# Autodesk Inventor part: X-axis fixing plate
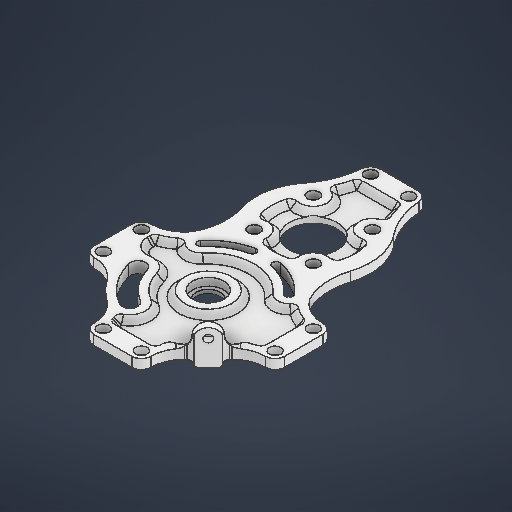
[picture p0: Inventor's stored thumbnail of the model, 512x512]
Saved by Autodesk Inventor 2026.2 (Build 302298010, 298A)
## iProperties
Created: 2026-04
Part Number: X-axis fixing plate
Material: PBT 플라스틱
Document SubType Name: Modeling
Designer: work
Density: 1.31 g/cm^3
Appearance: 매끄러움 - 흰색
Author: work
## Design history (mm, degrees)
sketch "스케치1"
  geometry: L1 (0, 0)-(0, -55); L2 (-15.5, -39.5)-(15.5, -39.5); L3 (15.5, -39.5)-(15.5, -70.5); L4 (15.5, -70.5)-(-15.5, -70.5); L5 (-15.5, -70.5)-(-15.5, -39.5); L6 (-15.5, -39.5)-(15.5, -70.5); L7 (15.5, -39.5)-(-15.5, -70.5); L8 (0, 0)-(22.981, -19.284); L9 (0, 0)-(30, 0); L10 (0, 0)-(6.237, -29.344); L11 (0, 0)-(-6.237, -29.344); L12 (-10, -95)-(10, -95); L13 (0, -55)-(0, -95); L14 (0, 0)-(45, 0); L15 (-10, -95)-(10, -95); L16 (-10, -100)-(10, -100); L17 (10, -90)-(-10, -90); L18 (10, 50)-(-10, 50); L19 (-10, 45)-(10, 45); L20 (-10, 45)-(10, 45); L21 (-10, 40)-(10, 40); L22 (0, 0)-(0, 45); L23 (0, 0)-(-45, 0); L24 (-45, -10)-(-45, 10); L25 (-40, -10)-(-40, 10); L26 (-50, 10)-(-50, -10); L27 (-45, -10)-(-45, 10); L28 (0, 0)-(0, -45); L29 (10, -45)-(-10, -45); L30 (10, -40)-(-10, -40); L31 (-10, -50)-(10, -50); L32 (10, -45)-(-10, -45); L33 (0, 0)-(45, 0); L34 (45, 10)-(45, -10); L35 (40, 10)-(40, -10); L36 (50, -10)-(50, 10); L37 (45, 10)-(45, -10); L38 (0, 0)-(-26.87, 26.87); L39 (-22.627, 31.113)-(-31.113, 22.627); L40 (-31.113, 22.627)-(-28.991, 20.506); L41 (-28.991, 20.506)-(-20.506, 28.991); L42 (-20.506, 28.991)-(-22.627, 31.113); L43 (0, 0)-(28.978, 7.765); L44 (0, 0)-(15, 25.981); C1 r 2.5 at (0, 0); C2 r 8.25 at (0, 0); C3 r 6.25 at (0, 0); C4 r 12.5 at (0, -55); C5 r 2 at (15.5, -39.5); C6 r 2 at (-15.5, -70.5); C7 r 2 at (15.5, -70.5); C8 r 2 at (-15.5, -39.5); C9 r 22 at (0, 0); C10 r 2 at (10, -95); C11 r 2 at (-10, -95); C12 r 2 at (10, 45); C13 r 2 at (-10, 45); C14 r 2 at (-45, 10); C15 r 2 at (-45, -10); C16 r 2 at (-10, -45); C17 r 2 at (10, -45); C18 r 2 at (45, -10); C19 r 2 at (45, 10); A1 r 30 centre (0, 0) between (6.237, -29.344) and (22.981, -19.284); A2 r 32 centre (0, 0) between (6.653, -31.301) and (24.513, -20.569); A3 r 28 centre (0, 0) between (5.822, -27.388) and (21.449, -17.998); A4 r 2 centre (6.237, -29.344) between (5.822, -27.388) and (6.653, -31.301); A5 r 2 centre (22.981, -19.284) between (24.513, -20.569) and (21.449, -17.998); A6 r 28 centre (0, 0) between (-21.449, -17.998) and (-5.822, -27.388); A7 r 30 centre (0, 0) between (-22.981, -19.284) and (-6.237, -29.344); A8 r 2 centre (-6.237, -29.344) between (-6.653, -31.301) and (-5.822, -27.388); A9 r 32 centre (0, 0) between (-24.513, -20.569) and (-6.653, -31.301); A10 r 2 centre (-22.981, -19.284) between (-21.449, -17.998) and (-24.513, -20.569); A11 r 38 centre (0, 0) between (22.258, 30.799) and (-26.87, 26.87); A12 r 30 centre (0, -55) between (-23.514, -73.63) and (28.562, -45.823); A13 r 5 centre (-10, -95) between (-10, -90) and (-10, -100); A14 r 5 centre (10, -95) between (10, -100) and (10, -90); A15 r 40 centre (-54.866, -98.471) between (-14.985, -95.386) and (-23.514, -73.63); A16 r 40 centre (54.866, -98.471) between (23.514, -73.63) and (14.985, -95.386); A17 r 5 centre (-10, 45) between (-10, 50) and (-10, 40); A18 r 5 centre (10, 45) between (10, 40) and (10, 50); A19 r 17.522 centre (32.522, 45) between (15, 45) and (22.258, 30.799); A20 r 17.522 centre (-32.522, 45) between (-22.258, 30.799) and (-15, 45); A21 r 17.522 centre (-45, -32.522) between (-30.799, -22.258) and (-45, -15); A22 r 5 centre (-45, -10) between (-50, -10) and (-40, -10); A23 r 5 centre (-45, 10) between (-40, 10) and (-50, 10); A24 r 17.522 centre (-45, 32.522) between (-45, 15) and (-30.799, 22.258); A25 r 17.522 centre (32.522, -45) between (22.258, -30.799) and (15, -45); A26 r 5 centre (10, -45) between (10, -50) and (10, -40); A27 r 5 centre (-10, -45) between (-10, -40) and (-10, -50); A28 r 17.522 centre (-32.522, -45) between (-15, -45) and (-22.258, -30.799); A29 r 17.522 centre (45, 32.522) between (30.799, 22.258) and (45, 15); A30 r 5 centre (45, 10) between (50, 10) and (40, 10); A31 r 5 centre (45, -10) between (40, -10) and (50, -10); A32 r 17.522 centre (45, -32.522) between (45, -15) and (30.799, -22.258); A33 r 30 centre (57.124, -36.646) between (30.799, -22.258) and (28.562, -45.823); A34 r 30 centre (-57.124, -36.646) between (-28.562, -45.823) and (-30.799, -22.258); A35 r 30 centre (0, 0) between (28.978, 7.765) and (15, 25.981); A36 r 34 centre (0, 0) between (32.841, 8.8) and (17, 29.445); A37 r 26 centre (0, 0) between (25.114, 6.729) and (13, 22.517); A38 r 4 centre (28.978, 7.765) between (25.114, 6.729) and (32.841, 8.8); A39 r 4 centre (15, 25.981) between (17, 29.445) and (13, 22.517); 17 further points
  constraints: 98 end point, 80 point on circle, 58 centre point, 23 coincident, 21 tangent, 14 symmetric about line, 8 midpoint, 7 equal length, 5 horizontal, 5 perpendicular, 3 vertical, 2 point on line, 121 other
  dimensions: "d0" = 5 diameter of C1; "d1" = 16.5 diameter of C2; "d2" = 2 radial gap between concentric circles of C2 C3; "d3" = 55 distance of L1.start L1.end; "d4" = 25 diameter of C4; "d5" = 31 distance of L3.end L4.end; "d6" = 31 distance of L2.end L3.end; "d7" = 4 diameter of C5; "d9" = 4 diameter of C6; "d10" = 4 diameter of C7; "d11" = 4 diameter of C8; "d14" = 44 diameter of C9; "d15" = 30 radius of A1; "d16" = 40 deg angle of L8 L9; "d17" = 38 deg angle of L10 L8; "d18" = 4 diameter of A4; "d19" = 8 radial gap between concentric circles of A11 A1; "d20" = 60 diameter of A12; "d21" = 20 distance of L12.start L12.end; "d22" = 45 distance of L14.start L14.end; "d23" = 40 distance of L13.start L13.end; "d24" = 4 diameter of C10; "d25" = 4 diameter of C11; "d26" = 5 radius of A14; "d27" = 40 radius of A15; "d28" = 20 distance of L20.start L20.end; "d29" = 4 diameter of C12; "d30" = 4 diameter of C13; "d31" = 5 radius of A18; "d32" = 45 distance of L14.start L22.end; "d35" = 360 deg dimension on C9.centre L22.end (derived); "d37" = 30 radius of A33; "d38" = 45 deg angle of L22 L38; "d39" = 12 distance of L40.end L41.end; "d40" = 3 distance of L39.end L40.end; "d41" = 30 radius of A35; "d42" = 45 deg angle of L43 L44; "d43" = 8 diameter of A38; "d44" = 30 deg angle of L22 L44
  node "스케치 - 원형 패턴1" dims "d35" = 360 deg (derived)
extrude "돌출1" new body sketch "스케치1" distance "d45" = 6; taper "d46" = 0 deg
extrude "돌출2" join sketch "스케치1" distance "d47" = 18; taper "d48" = 0 deg
extrude "돌출3" join sketch "스케치1" distance "d49" = 2; taper "d50" = 0 deg
sketch "스케치2"
  geometry: L1 (-50, 10)-(-50, -10) reference; L2 (-10, -50)-(10, -50) reference; L3 (22.29, -30.776)-(20.506, -28.991) reference; L4 (20.506, -28.991)-(28.991, -20.506) reference; L5 (28.991, -20.506)-(30.776, -22.29) reference; L6 (50, -10)-(50, 10) reference; L7 (10, 100)-(-10, 100) reference; C1 r 2 at (10, 95) reference; C2 r 2 at (-10, 95) reference; C3 r 2 at (10, -45) reference; C4 r 2 at (-10, -45) reference; C5 r 2 at (45, 10) reference; C6 r 2 at (45, -10) reference; C7 r 2 at (-45, -10) reference; C8 r 2 at (-45, 10) reference; C9 r 12.5 at (0, 55) reference; C10 r 2 at (-15.5, 39.5) reference; C11 r 2 at (15.5, 70.5) reference; C12 r 2 at (-15.5, 70.5) reference; C13 r 2 at (15.5, 39.5) reference; C14 r 8.25 at (0, 0) reference; A1 r 17.522 centre (-45, 32.522) between (-45, 15) and (-30.799, 22.258) reference; A2 r 5 centre (-45, 10) between (-45, 15) and (-50, 10) reference; A3 r 5 centre (-45, -10) between (-50, -10) and (-45, -15) reference; A4 r 17.522 centre (-45, -32.522) between (-30.799, -22.258) and (-45, -15) reference; A5 r 38 centre (0, 0) between (-30.799, -22.258) and (-22.258, -30.799) reference; A6 r 17.522 centre (-32.522, -45) between (-15, -45) and (-22.258, -30.799) reference; A7 r 5 centre (-10, -45) between (-15, -45) and (-10, -50) reference; A8 r 5 centre (10, -45) between (10, -50) and (15, -45) reference; A9 r 17.522 centre (32.522, -45) between (22.258, -30.799) and (15, -45) reference; A10 r 38 centre (0, 0) between (22.258, -30.799) and (22.29, -30.776) reference; A11 r 38 centre (0, 0) between (30.776, -22.29) and (30.799, -22.258) reference; A12 r 17.522 centre (45, -32.522) between (45, -15) and (30.799, -22.258) reference; A13 r 5 centre (45, -10) between (45, -15) and (50, -10) reference; A14 r 5 centre (45, 10) between (50, 10) and (45, 15) reference; A15 r 17.522 centre (45, 32.522) between (30.799, 22.258) and (45, 15) reference; A16 r 30 centre (57.124, 36.646) between (28.562, 45.823) and (30.799, 22.258) reference; A17 r 30 centre (0, 55) between (28.562, 45.823) and (23.514, 73.63) reference; A18 r 40 centre (54.866, 98.471) between (14.985, 95.386) and (23.514, 73.63) reference; A19 r 5 centre (10, 95) between (14.985, 95.386) and (10, 100) reference; A20 r 5 centre (-10, 95) between (-10, 100) and (-14.985, 95.386) reference; A21 r 40 centre (-54.866, 98.471) between (-23.514, 73.63) and (-14.985, 95.386) reference; A22 r 30 centre (0, 55) between (-23.514, 73.63) and (-28.562, 45.823) reference; A23 r 32 centre (0, 0) between (24.513, 20.569) and (6.653, 31.301) reference; A24 r 2 centre (22.981, 19.284) between (21.449, 17.998) and (24.513, 20.569) reference; A25 r 28 centre (0, 0) between (21.449, 17.998) and (5.822, 27.388) reference; A26 r 2 centre (6.237, 29.344) between (6.653, 31.301) and (5.822, 27.388) reference; A27 r 32 centre (0, 0) between (-6.653, 31.301) and (-24.513, 20.569) reference; A28 r 2 centre (-6.237, 29.344) between (-5.822, 27.388) and (-6.653, 31.301) reference; A29 r 28 centre (0, 0) between (-5.822, 27.388) and (-21.449, 17.998) reference; A30 r 2 centre (-22.981, 19.284) between (-24.513, 20.569) and (-21.449, 17.998) reference; A31 r 26 centre (0, 0) between (-25.114, -6.729) and (-13, -22.517) reference; A32 r 4 centre (-15, -25.981) between (-17, -29.445) and (-13, -22.517) reference; A33 r 34 centre (0, 0) between (-32.841, -8.8) and (-17, -29.445) reference; A34 r 4 centre (-28.978, -7.765) between (-25.114, -6.729) and (-32.841, -8.8) reference; A35 r 30 centre (-57.124, 36.646) between (-30.799, 22.258) and (-28.562, 45.823) reference; 11 further points
  constraints: 10 coincident
hole "구멍1" sketch "스케치2" at (-10, -45), (10, -45), (-45, -10), (-45, 10), (15.5, 39.5), (-15.5, 39.5), (15.5, 70.5), (-15.5, 70.5), (10, 95), (-10, 95), (45, 10), (45, -10) diameter "d51" = 4; stored, may be unused: countersink angle "d55" = 90 deg, drill point angle "d57" = 0 deg; dims "d52" = 6, "d53" = 6.2, "d54" = 4, "d56" = 8
sketch "스케치3"
  geometry: L1 (-6, 0)-(-6, 18); L2 (-12, 18)-(0, 18) reference; C1 r 2 at (-6, 13)
  constraints: 2 end point, 1 centre point, 1 midpoint, 1 point on line
  dimensions: "d58" = 4 diameter of C1; "d59" = 5 distance from line of L2 C1.centre
extrude "돌출4" cut sketch "스케치3" distance "d60" = 6; taper "d61" = 0 deg
fillet "모깎기1" dims "d62" = 6
sketch "스케치4"
  geometry: L1 (16.263, -33.234)-(18.091, -35.062) reference; L2 (16.263, -33.234)-(33.234, -16.263) reference; L3 (35.062, -18.091)-(33.234, -16.263) reference; L4 (50, -10)-(50, 10) reference; L5 (10, 100)-(-10, 100) reference; L6 (-50, 10)-(-50, -10) reference; L7 (-10, -50)-(10, -50) reference; L8 (-10, 96)-(10, 96); L9 (46, 10)-(46, -10); L10 (35.727, -13.1)-(33.234, -10.607); L11 (33.234, -10.607)-(10.607, -33.234); L12 (10.607, -33.234)-(13.1, -35.727); L13 (10, -46)-(-10, -46); L14 (-46, -10)-(-46, 10); L15 (-10, -45)-(10, -45); L16 (-10, -40)-(10, -40); L17 (10, -50)-(-10, -50); L18 (-45, -10)-(-45, 10); L19 (-40, -10)-(-40, 10); L20 (-50, 10)-(-50, -10); L21 (45, -10)-(45, 10); L22 (50, -10)-(50, 10); L23 (40, 10)-(40, -10); L24 (10, 95)-(-10, 95); L25 (10, 100)-(-10, 100); L26 (-10, 90)-(10, 90); L27 (0, 55)-(0, 0); C1 r 6.25 at (0, 0) reference; C2 r 12.25 at (0, 0); C3 r 8.25 at (0, 0) reference; C4 r 8.25 at (0, 0) reference; C5 r 12.5 at (0, 55) reference; C6 r 3.1 at (-10, -45) reference; C7 r 3.1 at (10, -45) reference; C8 r 3.1 at (-45, -10) reference; C9 r 3.1 at (-45, 10) reference; C10 r 3.1 at (15.5, 39.5) reference; C11 r 3.1 at (-15.5, 39.5) reference; C12 r 3.1 at (15.5, 70.5) reference; C13 r 3.1 at (-15.5, 70.5) reference; C14 r 3.1 at (10, 95) reference; C15 r 3.1 at (-10, 95) reference; C16 r 3.1 at (45, 10) reference; C17 r 3.1 at (45, -10) reference; C18 r 36 at (0, 0); C19 r 7.1 at (-15.5, 39.5); C20 r 7.1 at (-15.5, 70.5); C21 r 7.1 at (15.5, 70.5); C22 r 2 at (-10, -45) reference; C23 r 2 at (-45, -10) reference; A1 r 26 centre (0, 0) between (-25.114, -6.729) and (-13, -22.517) reference; A2 r 4 centre (-15, -25.981) between (-17, -29.445) and (-13, -22.517) reference; A3 r 34 centre (0, 0) between (-32.841, -8.8) and (-17, -29.445) reference; A4 r 4 centre (-28.978, -7.765) between (-25.114, -6.729) and (-32.841, -8.8) reference; A5 r 32 centre (0, 0) between (-6.653, 31.301) and (-24.513, 20.569) reference; A6 r 2 centre (-6.237, 29.344) between (-5.822, 27.388) and (-6.653, 31.301) reference; A7 r 28 centre (0, 0) between (-5.822, 27.388) and (-21.449, 17.998) reference; A8 r 2 centre (-22.981, 19.284) between (-24.513, 20.569) and (-21.449, 17.998) reference; A9 r 32 centre (0, 0) between (24.513, 20.569) and (6.653, 31.301) reference; A10 r 2 centre (22.981, 19.284) between (21.449, 17.998) and (24.513, 20.569) reference; A11 r 28 centre (0, 0) between (21.449, 17.998) and (5.822, 27.388) reference; A12 r 2 centre (6.237, 29.344) between (6.653, 31.301) and (5.822, 27.388) reference; A13 r 17.522 centre (45, -32.522) between (45, -15) and (35.062, -18.091) reference; A14 r 5 centre (45, -10) between (45, -15) and (50, -10) reference; A15 r 5 centre (45, 10) between (50, 10) and (45, 15) reference; A16 r 17.522 centre (45, 32.522) between (30.799, 22.258) and (45, 15) reference; A17 r 30 centre (57.124, 36.646) between (28.562, 45.823) and (30.799, 22.258) reference; A18 r 30 centre (0, 55) between (28.562, 45.823) and (23.514, 73.63) reference; A19 r 40 centre (54.866, 98.471) between (14.985, 95.386) and (23.514, 73.63) reference; A20 r 5 centre (10, 95) between (14.985, 95.386) and (10, 100) reference; A21 r 5 centre (-10, 95) between (-10, 100) and (-14.985, 95.386) reference; A22 r 40 centre (-54.866, 98.471) between (-23.514, 73.63) and (-14.985, 95.386) reference; A23 r 30 centre (0, 55) between (-23.514, 73.63) and (-28.562, 45.823) reference; A24 r 30 centre (-57.124, 36.646) between (-30.799, 22.258) and (-28.562, 45.823) reference; A25 r 17.522 centre (-45, 32.522) between (-45, 15) and (-30.799, 22.258) reference; A26 r 5 centre (-45, 10) between (-45, 15) and (-50, 10) reference; A27 r 5 centre (-45, -10) between (-50, -10) and (-45, -15) reference; A28 r 17.522 centre (-45, -32.522) between (-30.799, -22.258) and (-45, -15) reference; A29 r 38 centre (0, 0) between (-30.799, -22.258) and (-22.258, -30.799) reference; A30 r 17.522 centre (-32.522, -45) between (-15, -45) and (-22.258, -30.799) reference; A31 r 5 centre (-10, -45) between (-15, -45) and (-10, -50) reference; A32 r 5 centre (10, -45) between (10, -50) and (15, -45) reference; A33 r 17.522 centre (32.522, -45) between (18.091, -35.062) and (15, -45) reference; A34 r 22 centre (0, 0) between (-21.25, -5.694) and (-11, -19.053); A35 r 8 centre (-28.978, -7.765) between (-21.25, -5.694) and (-36.705, -9.835); A36 r 38 centre (0, 0) between (-36.705, -9.835) and (-19, -32.909); A37 r 8 centre (-15, -25.981) between (-19, -32.909) and (-11, -19.053); A38 r 36 centre (0, 0) between (-7.485, 35.213) and (-27.578, 23.14); A39 r 6 centre (-6.237, 29.344) between (-4.99, 23.476) and (-7.485, 35.213); A40 r 24 centre (0, 0) between (-4.99, 23.476) and (-18.385, 15.427); A41 r 6 centre (-22.981, 19.284) between (-27.578, 23.14) and (-18.385, 15.427); A42 r 24 centre (0, 0) between (18.385, 15.427) and (4.99, 23.476); A43 r 6 centre (22.981, 19.284) between (18.385, 15.427) and (27.578, 23.14); A44 r 36 centre (0, 0) between (27.578, 23.14) and (7.485, 35.213); A45 r 6 centre (6.237, 29.344) between (7.485, 35.213) and (4.99, 23.476); A46 r 21.92 centre (0, 55) between (-15.5, 39.5) and (19.641, 45.267); A47 r 26 centre (0, 55) between (-20.379, 71.146) and (-24.754, 47.046); A48 r 44 centre (-54.866, 98.471) between (-20.379, 71.146) and (-10.997, 95.077); A49 r 1 centre (-10, 95) between (-10, 96) and (-10.997, 95.077); A50 r 1 centre (10, 95) between (10.997, 95.077) and (10, 96); A51 r 44 centre (54.866, 98.471) between (10.997, 95.077) and (20.379, 71.146); A52 r 26 centre (0, 55) between (24.754, 47.046) and (20.379, 71.146); A53 r 34 centre (57.124, 36.646) between (24.754, 47.046) and (27.408, 20.124); A54 r 21.522 centre (45, 32.522) between (27.408, 20.124) and (45, 11); A55 r 1 centre (45, 10) between (46, 10) and (45, 11); A56 r 1 centre (45, -10) between (45, -11) and (46, -10); A57 r 21.522 centre (45, -32.522) between (45, -11) and (35.727, -13.1); A58 r 21.522 centre (32.522, -45) between (13.1, -35.727) and (11, -45); A59 r 1 centre (10, -45) between (10, -46) and (11, -45); A60 r 1 centre (-10, -45) between (-11, -45) and (-10, -46); A61 r 21.522 centre (-32.522, -45) between (-11, -45) and (-19.915, -27.557); A62 r 34 centre (0, 0) between (-27.557, -19.915) and (-19.915, -27.557); A63 r 21.522 centre (-45, -32.522) between (-27.557, -19.915) and (-45, -11); A64 r 1 centre (-45, -10) between (-46, -10) and (-45, -11)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; 31 further points
  constraints: 89 point on circle, 49 centre point, 48 end point, 17 tangent, 7 parallel, 4 midpoint, 3 coincident, 3 symmetric about line, 2 vertical, 41 other
  dimensions: "d63" = 4 radial gap between concentric circles of C2 C3; "d64" = 0 radial gap between concentric circles of A29 A36; "d65" = 4 radial gap between concentric circles of A5 A38; "d66" = 72 diameter of C18; "d67" = 4 radial gap between concentric circles of A12 A45; "d68" = 4 radial gap between concentric circles of C11 C19; "d69" = 4 radial gap between concentric circles of C13 C20; "d70" = 4 radial gap between concentric circles of C12 C21; "d71" = 4 dimension on C10; "d72" = 4 radial gap between concentric circles of A23 A47; "d73" = 5 radius of A68; "d74" = 10 diameter of A71; "d75" = 10 diameter of A73; "d76" = 10 diameter of A75
extrude "돌출5" cut sketch "스케치4" distance "d77" = 3; taper "d78" = 0 deg
fillet "모깎기2" dims "d79" = 3
sketch "스케치5"
  geometry: L1 (40, 9.342)-(40, -9.342) reference; L2 (-9.287, 90)-(9.287, 90) reference; L3 (-40, -10)-(-40, 9.342) reference; L4 (9.342, -40)-(-9.342, -40) reference; L5 (30.45, -19.048)-(19.048, -30.45) reference; C1 r 12.5 at (0, 55) reference; C2 r 12.25 at (0, 0) reference; C3 r 20.403 at (0, 55); A1 r 6 centre (6.237, 29.344) between (5.726, 35.323) and (4.99, 23.476) reference; A2 r 3 centre (35.043, -10.113) between (35.284, -13.103) and (36.261, -12.854) reference; A3 r 21.522 centre (45, -32.522) between (37.979, -12.178) and (36.261, -12.854) reference; A4 r 3 centre (37, -9.342) between (37.979, -12.178) and (40, -9.342) reference; A5 r 3 centre (37, 9.342) between (40, 9.342) and (37.979, 12.178) reference; A6 r 21.522 centre (45, 32.522) between (31.601, 15.68) and (37.979, 12.178) reference; A7 r 3 centre (29.733, 13.332) between (31.601, 15.68) and (27.482, 15.316) reference; A8 r 6 centre (22.981, 19.284) between (18.385, 15.427) and (27.482, 15.316) reference; A9 r 24 centre (0, 0) between (18.385, 15.427) and (4.99, 23.476) reference; A10 r 6 centre (6.237, 29.344) between (5.726, 35.323) and (4.99, 23.476) reference; A11 r 3 centre (5.47, 38.312) between (5.726, 35.323) and (8.449, 38.665) reference; A12 r 7.1 centre (15.5, 39.5) between (17.281, 46.373) and (8.449, 38.665) reference; A13 r 3 centre (18.034, 49.277) between (17.281, 46.373) and (20.893, 48.37) reference; A14 r 21.92 centre (0, 55) between (20.893, 48.37) and (20.893, 61.63) reference; A15 r 3 centre (18.034, 60.723) between (20.893, 61.63) and (17.281, 63.627) reference; A16 r 7.1 centre (15.5, 70.5) between (12.834, 77.08) and (17.281, 63.627) reference; A17 r 3 centre (11.707, 79.861) between (12.834, 77.08) and (14.462, 81.049) reference; A18 r 44 centre (54.866, 98.471) between (12.197, 87.732) and (14.462, 81.049) reference; A19 r 3 centre (9.287, 87) between (12.197, 87.732) and (9.287, 90) reference; A20 r 3 centre (-9.287, 87) between (-9.287, 90) and (-12.197, 87.732) reference; A21 r 44 centre (-54.866, 98.471) between (-14.462, 81.049) and (-12.197, 87.732) reference; A22 r 3 centre (-11.707, 79.861) between (-14.462, 81.049) and (-12.834, 77.08) reference; A23 r 7.1 centre (-15.5, 70.5) between (-17.281, 63.627) and (-12.834, 77.08) reference; A24 r 3 centre (-18.034, 60.723) between (-17.281, 63.627) and (-20.893, 61.63) reference; A25 r 21.92 centre (0, 55) between (-20.893, 61.63) and (-20.893, 48.37) reference; A26 r 3 centre (-18.034, 49.277) between (-20.893, 48.37) and (-17.281, 46.373) reference; A27 r 7.1 centre (-15.5, 39.5) between (-8.449, 38.665) and (-17.281, 46.373) reference; A28 r 3 centre (-5.47, 38.312) between (-8.449, 38.665) and (-5.726, 35.323) reference; A29 r 6 centre (-6.237, 29.344) between (-4.99, 23.476) and (-5.726, 35.323) reference; A30 r 24 centre (0, 0) between (-4.99, 23.476) and (-18.385, 15.427) reference; A31 r 6 centre (-22.981, 19.284) between (-27.482, 15.316) and (-18.385, 15.427) reference; A32 r 3 centre (-29.733, 13.332) between (-27.482, 15.316) and (-31.601, 15.68) reference; A33 r 21.522 centre (-45, 32.522) between (-37.979, 12.178) and (-31.601, 15.68) reference; A34 r 3 centre (-37, 9.342) between (-37.979, 12.178) and (-40, 9.342) reference; A35 r 8 centre (-28.978, -7.765) between (-21.25, -5.694) and (-36.705, -9.835) reference; A36 r 22 centre (0, 0) between (-21.25, -5.694) and (-11, -19.053) reference; A37 r 8 centre (-15, -25.981) between (-11.244, -33.044) and (-11, -19.053) reference; A38 r 3 centre (-9.835, -35.693) between (-11.244, -33.044) and (-12.61, -36.831) reference; A39 r 21.522 centre (-32.522, -45) between (-12.178, -37.979) and (-12.61, -36.831) reference; A40 r 3 centre (-9.342, -37) between (-12.178, -37.979) and (-9.342, -40) reference; A41 r 3 centre (9.342, -37) between (9.342, -40) and (12.178, -37.979) reference; A42 r 21.522 centre (32.522, -45) between (12.36, -37.47) and (12.178, -37.979) reference; A43 r 3 centre (9.55, -36.42) between (12.36, -37.47) and (12.533, -36.1) reference; A44 r 3 centre (15.516, -35.781) between (14.322, -33.028) and (12.533, -36.1) reference; A45 r 36 centre (0, 0) between (14.322, -33.028) and (18.465, -30.904) reference; A46 r 3 centre (16.927, -28.328) between (18.465, -30.904) and (19.048, -30.45) reference; A47 r 3 centre (28.328, -16.927) between (30.45, -19.048) and (30.904, -18.465) reference; A48 r 36 centre (0, 0) between (30.904, -18.465) and (32.792, -14.855) reference; A49 r 3 centre (35.525, -16.093) between (35.284, -13.103) and (32.792, -14.855) reference; A50 r 21.522 centre (-45, -32.522) between (-35.658, -13.133) and (-40.241, -11.533) reference; A51 r 38 centre (0, 0) between (-36.705, -9.835) and (-35.658, -13.133) reference; A52 r 5 centre (-45, -10) between (-40.241, -11.533) and (-40, -10) reference; 5 further points
  constraints: 2 coincident, 1 centre point, 1 tangent, 3 other
extrude "돌출6" join sketch "스케치5" distance "d80" = 3; taper "d81" = 0 deg
sketch "스케치6"
  geometry: L1 (-40, -10)-(-40, 9.342) reference; L2 (-40, -10)-(-40, 9.342) reference; L3 (-40, -10)-(-40, 9.342) reference; L4 (9.342, -40)-(-9.342, -40) reference; L5 (30.45, -19.048)-(19.048, -30.45) reference; L6 (40, 9.342)-(40, -9.342) reference; C1 r 12.25 at (0, 0) reference; A1 r 8 centre (-28.978, -7.765) between (-21.25, -5.694) and (-36.705, -9.835) reference; A2 r 8 centre (-32, 7.947) between (-40, 7.947) and (-30.489, 0.091); A3 r 24 centre (0, 0) between (18.385, 15.427) and (-18.385, 15.427) reference; A4 r 6 centre (-22.981, 19.284) between (-27.482, 15.316) and (-18.385, 15.427) reference; A5 r 3 centre (-29.733, 13.332) between (-27.482, 15.316) and (-31.601, 15.68) reference; A6 r 21.522 centre (-45, 32.522) between (-37.979, 12.178) and (-31.601, 15.68) reference; A7 r 3 centre (-37, 9.342) between (-37.979, 12.178) and (-40, 9.342) reference; A8 r 5 centre (-45, -10) between (-40.241, -11.533) and (-40, -10) reference; A9 r 21.522 centre (-45, -32.522) between (-35.658, -13.133) and (-40.241, -11.533) reference; A10 r 38 centre (0, 0) between (-36.705, -9.835) and (-35.658, -13.133) reference; A11 r 8 centre (-28.978, -7.765) between (-21.25, -5.694) and (-36.705, -9.835) reference; A12 r 22 centre (0, 0) between (-21.25, -5.694) and (-11, -19.053) reference; A13 r 8 centre (-15, -25.981) between (-11.244, -33.044) and (-11, -19.053) reference; A14 r 3 centre (-9.835, -35.693) between (-11.244, -33.044) and (-12.61, -36.831) reference; A15 r 21.522 centre (-32.522, -45) between (-12.178, -37.979) and (-12.61, -36.831) reference; A16 r 3 centre (-9.342, -37) between (-12.178, -37.979) and (-9.342, -40) reference; A17 r 3 centre (9.342, -37) between (9.342, -40) and (12.178, -37.979) reference; A18 r 21.522 centre (32.522, -45) between (12.36, -37.47) and (12.178, -37.979) reference; A19 r 3 centre (9.55, -36.42) between (12.36, -37.47) and (12.533, -36.1) reference; A20 r 3 centre (15.516, -35.781) between (14.322, -33.028) and (12.533, -36.1) reference; A21 r 36 centre (0, 0) between (14.322, -33.028) and (18.465, -30.904) reference; A22 r 3 centre (16.927, -28.328) between (18.465, -30.904) and (19.048, -30.45) reference; A23 r 3 centre (28.328, -16.927) between (30.45, -19.048) and (30.904, -18.465) reference; A24 r 36 centre (0, 0) between (30.904, -18.465) and (32.792, -14.855) reference; A25 r 3 centre (35.525, -16.093) between (35.284, -13.103) and (32.792, -14.855) reference; A26 r 3 centre (35.043, -10.113) between (35.284, -13.103) and (36.261, -12.854) reference; A27 r 21.522 centre (45, -32.522) between (37.979, -12.178) and (36.261, -12.854) reference; A28 r 3 centre (37, -9.342) between (37.979, -12.178) and (40, -9.342) reference; A29 r 3 centre (37, 9.342) between (40, 9.342) and (37.979, 12.178) reference; A30 r 21.522 centre (45, 32.522) between (31.601, 15.68) and (37.979, 12.178) reference; A31 r 3 centre (29.733, 13.332) between (31.601, 15.68) and (27.482, 15.316) reference; A32 r 6 centre (22.981, 19.284) between (18.385, 15.427) and (27.482, 15.316) reference; 3 further points
  constraints: 3 point on circle, 2 tangent, 1 centre point, 1 point on line
  dimensions: "d85" = 8 radius of A2
extrude "돌출7" join sketch "스케치6" distance "d86" = 3; taper "d87" = 0 deg
chamfer "모따기2" distance "d88" = 3; stored, may be unused: second distance "d89" = 2, angle "d90" = 45 deg
sketch "스케치7"
  geometry: L1 (0, 14.756)-(0, 0) reference; L2 (-10.659, 0)-(-10.659, 14.756) reference; L3 (-10.659, 0)-(0, 0) reference; C1 r 2 at (-5.33, 13) reference; A1 r 6 centre (-5.33, 12) between (0, 14.756) and (-10.659, 14.756) reference; 1 further point
extrude "돌출8" join sketch "스케치7" distance "d91" = 3; taper "d92" = 0 deg
fillet "모깎기3" dims "d93" = 3
sketch "스케치8"
  geometry: L1 (8.062, -6)-(-8.062, -6) reference; L2 (12, -6)-(8.062, -6) reference; L3 (-8.062, -6)-(-12, -6) reference; C1 r 2 at (0, 1) reference; A1 r 6 centre (12, 0) between (6, 0) and (12, -6) reference; A2 r 6 centre (0, 0) between (6, 0) and (-6, 0) reference; A3 r 6 centre (-12, 0) between (-12, -6) and (-6, 0) reference; 1 further point
extrude "돌출9" cut sketch "스케치8" distance "d94" = 2; taper "d95" = 0 deg
fillet "모깎기4" dims "d96" = 3
chamfer "모따기3" distance "d97" = 3; stored, may be unused: second distance "d98" = 2, angle "d99" = 45 deg
chamfer "모따기4" distance "d100" = 1; stored, may be unused: second distance "d101" = 2, angle "d102" = 45 deg
sketch "스케치9"
  geometry: L1 (32.053, 25.93)-(31.583, 25.46) reference; L2 (25.93, 32.053)-(32.053, 25.93) reference; L3 (25.46, 31.583)-(25.93, 32.053) reference; L4 (-10, 49)-(10, 49) reference; L5 (-49, -10)-(-49, 10) reference; L6 (10, -99)-(-10, -99) reference; L7 (49, 10)-(49, -10) reference; C1 r 6.25 at (0, 0) reference; C2 r 2 at (10, -95) reference; C3 r 2 at (-10, -95) reference; C4 r 2 at (10, 45) reference; C5 r 2 at (-10, 45) reference; C6 r 2 at (45, -10) reference; C7 r 2 at (45, 10) reference; C8 r 2 at (-45, 10) reference; C9 r 2 at (-45, -10) reference; C10 r 12.5 at (0, -55) reference; C11 r 2 at (-15.5, -39.5) reference; C12 r 2 at (15.5, -70.5) reference; C13 r 2 at (-15.5, -70.5) reference; C14 r 2 at (15.5, -39.5) reference; A1 r 4 centre (22.631, 34.411) between (20.306, 31.156) and (25.46, 31.583) reference; A2 r 7 centre (24.375, 36.853) between (19.425, 31.903) and (20.306, 31.156) reference; A3 r 18.522 centre (32.522, 45) between (14, 45) and (19.425, 31.903) reference; A4 r 4 centre (10, 45) between (14, 45) and (10, 49) reference; A5 r 4 centre (-10, 45) between (-10, 49) and (-14, 45) reference; A6 r 18.522 centre (-32.522, 45) between (-21.673, 29.988) and (-14, 45) reference; A7 r 37 centre (0, 0) between (-21.673, 29.988) and (-29.988, 21.673) reference; A8 r 18.522 centre (-45, 32.522) between (-45, 14) and (-29.988, 21.673) reference; A9 r 4 centre (-45, 10) between (-45, 14) and (-49, 10) reference; A10 r 4 centre (-45, -10) between (-49, -10) and (-45, -14) reference; A11 r 18.522 centre (-45, -32.522) between (-30.128, -21.482) and (-45, -14) reference; A12 r 4 centre (-33.339, -23.867) between (-29.816, -21.973) and (-30.128, -21.482) reference; A13 r 31 centre (-57.124, -36.646) between (-27.61, -46.129) and (-29.816, -21.973) reference; A14 r 29 centre (0, -55) between (-27.61, -46.129) and (-22.73, -73.009) reference; A15 r 41 centre (-54.866, -98.471) between (-13.988, -95.309) and (-22.73, -73.009) reference; A16 r 4 centre (-10, -95) between (-13.988, -95.309) and (-10, -99) reference; A17 r 4 centre (10, -95) between (10, -99) and (13.988, -95.309) reference; A18 r 41 centre (54.866, -98.471) between (22.73, -73.009) and (13.988, -95.309) reference; A19 r 29 centre (0, -55) between (22.73, -73.009) and (27.61, -46.129) reference; A20 r 31 centre (57.124, -36.646) between (29.816, -21.973) and (27.61, -46.129) reference; A21 r 4 centre (33.339, -23.867) between (30.128, -21.482) and (29.816, -21.973) reference; A22 r 18.522 centre (45, -32.522) between (45, -14) and (30.128, -21.482) reference; A23 r 4 centre (45, -10) between (45, -14) and (49, -10) reference; A24 r 4 centre (45, 10) between (49, 10) and (45, 14) reference; A25 r 18.522 centre (45, 32.522) between (31.903, 19.425) and (45, 14) reference; A26 r 7 centre (36.853, 24.375) between (31.156, 20.306) and (31.903, 19.425) reference; A27 r 4 centre (34.411, 22.631) between (31.583, 25.46) and (31.156, 20.306) reference; A28 r 32 centre (0, 0) between (6.653, -31.301) and (24.513, -20.569) reference; A29 r 2 centre (6.237, -29.344) between (5.822, -27.388) and (6.653, -31.301) reference; A30 r 28 centre (0, 0) between (5.822, -27.388) and (21.449, -17.998) reference; A31 r 2 centre (22.981, -19.284) between (24.513, -20.569) and (21.449, -17.998) reference; A32 r 32 centre (0, 0) between (-24.513, -20.569) and (-6.653, -31.301) reference; A33 r 2 centre (-22.981, -19.284) between (-21.449, -17.998) and (-24.513, -20.569) reference; A34 r 28 centre (0, 0) between (-21.449, -17.998) and (-5.822, -27.388) reference; A35 r 2 centre (-6.237, -29.344) between (-6.653, -31.301) and (-5.822, -27.388) reference; A36 r 26 centre (0, 0) between (-13, 22.517) and (-25.114, 6.729) reference; A37 r 4 centre (-28.978, 7.765) between (-32.841, 8.8) and (-25.114, 6.729) reference; A38 r 34 centre (0, 0) between (-17, 29.445) and (-32.841, 8.8) reference; A39 r 4 centre (-15, 25.981) between (-13, 22.517) and (-17, 29.445) reference; 1 further point
  node "투영된 루프7"
feature "Ӡ耀ӣ耀Ӧ耀ө耀Ӭ耀ӯ耀Ӳ耀ӵ耀" dims "d0" = 5, "d1" = 16.5, "d2" = 2, "d3" = 55, "d4" = 25, "d5" = 31, "d6" = 31, "d7" = 4, "d9" = 4, "d10" = 4, "d11" = 4, "d14" = 44, "d15" = 30, "d16" = 40 deg, "d17" = 38 deg, "d18" = 4, "d19" = 8, "d20" = 60, "d21" = 20, "d22" = 45, "d23" = 40, "d24" = 4, "d25" = 4, "d26" = 5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
node "솔리드1"
node "투영된 루프1"
node "투영된 루프2"
node "투영된 루프3"
node "투영된 루프4"
node "투영된 루프5"
node "투영된 루프6"
feature "A9D066F2-1C7D-4E18-AEED-F7BC21143FA4" dims "d51" = 4, "d52" = 6, "d53" = 6.2, "d54" = 4, "d55" = 90 deg, "d56" = 8, "d57" = 0
